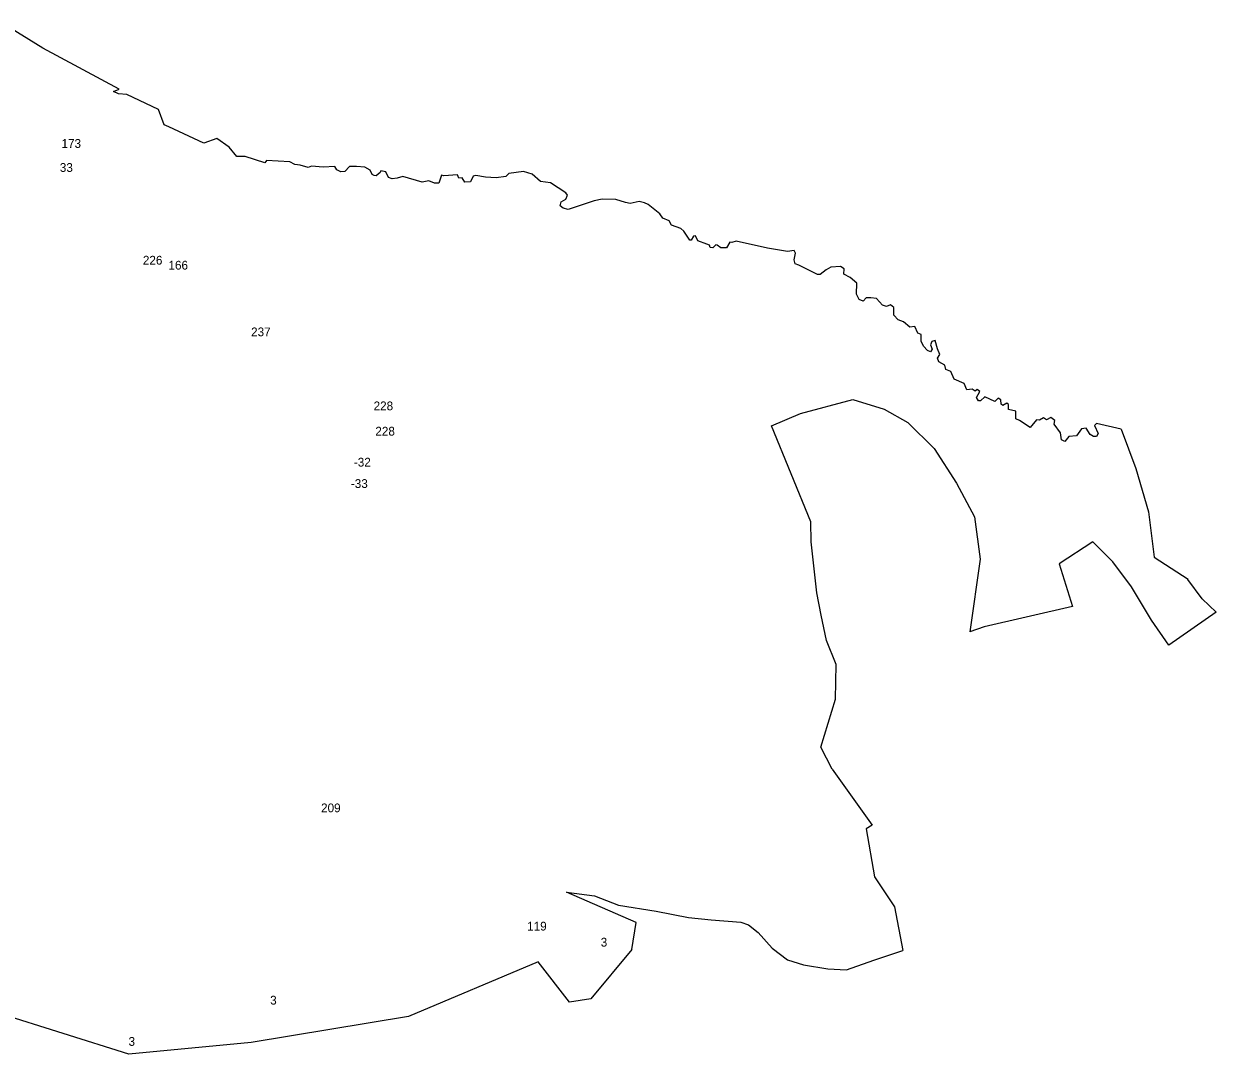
# Model space of a CAD drawing. Extents: x -788870 to -783053, y -967261 to -964403.
# Drawn here: x -784414 to -783053, y -967261 to -966085 of the extents above; entities that cross this region are included whole.
import ezdxf

# ---------------------------------------------------------------- set-up
doc = ezdxf.new("R2010")
doc.units = 0
doc.layers.add('Vrstva 13', color=7, linetype='Continuous')
doc.layers.add('Vrstva 15', color=7, linetype='Continuous')

msp = doc.modelspace()

# ---------------------------------------------------------------- linework, layer by layer
at = {"layer": 'Vrstva 13'}
for p, q in [((-784392.37, -966113.11), (-784437.41, -966085.29)), ((-784305.18, -966159.92), (-784392.37, -966113.11)), ((-784311.84, -966162.38), (-784305.18, -966159.92)), ((-784305.9, -966165.14), (-784311.84, -966162.38)), ((-784296.49, -966166.01), (-784305.9, -966165.14)), ((-784260.28, -966182.81), (-784296.49, -966166.01)), ((-784253.77, -966200.49), (-784260.28, -966182.81)), ((-784248.41, -966202.81), (-784253.77, -966200.49)), ((-784208.43, -966221.35), (-784248.41, -966202.81)), ((-784193.66, -966216.14), (-784208.43, -966221.35)), ((-784179.61, -966226.14), (-784193.66, -966216.14)), ((-784171.06, -966236.57), (-784179.61, -966226.14)), ((-784161.5, -966236.71), (-784171.06, -966236.57)), ((-784138.91, -966243.96), (-784161.5, -966236.71)), ((-784137.17, -966241.06), (-784138.91, -966243.96)), ((-784110.38, -966242.8), (-784137.17, -966241.06)), ((-784104.88, -966245.7), (-784110.38, -966242.8)), ((-784098.65, -966246.57), (-784104.88, -966245.7)), ((-784089.38, -966249.18), (-784098.65, -966246.57)), ((-784085.76, -966247.58), (-784089.38, -966249.18)), ((-784072.43, -966248.74), (-784085.76, -966247.58)), ((-784058.95, -966248.02), (-784072.43, -966248.74)), ((-784056.64, -966251.64), (-784058.95, -966248.02)), ((-784052.29, -966253.96), (-784056.64, -966251.64)), ((-784042.15, -966248.02), (-784047.51, -966253.53)), ((-784034.33, -966248.17), (-784042.15, -966248.02)), ((-784024.63, -966248.6), (-784034.33, -966248.17)), ((-784018.54, -966252.37), (-784024.63, -966248.6)), ((-784047.51, -966253.53), (-784052.29, -966253.96)), ((-784016.37, -966257), (-784018.54, -966252.37)), ((-784014.05, -966258.16), (-784016.37, -966257)), ((-784012.03, -966258.6), (-784014.05, -966258.16)), ((-784007.25, -966254.69), (-784012.03, -966258.6)), ((-784006.52, -966252.8), (-784007.25, -966254.69)), ((-784001.02, -966253.96), (-784006.52, -966252.8)), ((-783997.98, -966260.48), (-784001.02, -966253.96)), ((-783993.63, -966262.22), (-783997.98, -966260.48)), ((-783987.98, -966261.35), (-783993.63, -966262.22)), ((-783981.32, -966259.32), (-783987.98, -966261.35)), ((-783959.3, -966265.84), (-783981.32, -966259.32)), ((-783951.77, -966264.25), (-783959.3, -966265.84)), ((-783945.4, -966267.15), (-783951.77, -966264.25)), ((-783937.15, -966257.73), (-783940.48, -966266.86)), ((-783934.54, -966258.74), (-783937.15, -966257.73)), ((-783919.19, -966257.58), (-783934.54, -966258.74)), ((-783917.45, -966261.21), (-783919.19, -966257.58)), ((-783913.68, -966261.06), (-783917.45, -966261.21)), ((-783910.5, -966265.7), (-783913.68, -966261.06)), ((-783904.12, -966265.55), (-783910.5, -966265.7)), ((-783901.08, -966259.03), (-783904.12, -966265.55)), ((-783898.04, -966258.16), (-783901.08, -966259.03)), ((-783886.89, -966260.34), (-783898.04, -966258.16)), ((-783875.01, -966260.77), (-783886.89, -966260.34)), ((-783863.86, -966259.33), (-783875.01, -966260.77)), ((-783860.53, -966256.14), (-783863.86, -966259.33)), ((-783843.87, -966253.68), (-783860.53, -966256.14)), ((-783833.88, -966256.87), (-783843.87, -966253.68)), ((-783824.17, -966264.98), (-783833.88, -966256.87)), ((-783812.88, -966266.72), (-783824.17, -966264.98)), ((-783940.48, -966266.86), (-783945.4, -966267.15)), ((-783795.21, -966278.17), (-783812.88, -966266.72)), ((-783793.32, -966280.77), (-783795.21, -966278.17)), ((-783801.72, -966292.94), (-783800.56, -966288.16)), ((-783798.25, -966295.55), (-783801.72, -966292.94)), ((-783800.56, -966288.16), (-783795.35, -966285.12)), ((-783795.35, -966285.12), (-783793.32, -966280.77)), ((-783762.9, -966287), (-783792.89, -966297)), ((-783753.92, -966285.26), (-783762.9, -966287)), ((-783738.28, -966285.84), (-783753.92, -966285.26)), ((-783727.42, -966289.17), (-783738.28, -966285.84)), ((-783721.91, -966290.04), (-783727.42, -966289.17)), ((-783711.78, -966288.02), (-783721.91, -966290.04)), ((-783705.69, -966289.46), (-783711.78, -966288.02)), ((-783701.49, -966291.35), (-783705.69, -966289.46)), ((-783687.88, -966301.93), (-783701.49, -966291.35)), ((-783792.89, -966297), (-783798.25, -966295.55)), ((-783684.55, -966307.14), (-783687.88, -966301.93)), ((-783677.3, -966309.89), (-783684.55, -966307.14)), ((-783674.69, -966315.12), (-783677.3, -966309.89)), ((-783664.12, -966318.74), (-783674.69, -966315.12)), ((-783660.64, -966321.64), (-783664.12, -966318.74)), ((-783653.83, -966332.21), (-783660.64, -966321.64)), ((-783652.38, -966332.21), (-783653.83, -966332.21)), ((-783649.49, -966327.58), (-783652.38, -966332.21)), ((-783647.32, -966327.29), (-783649.49, -966327.58)), ((-783644.56, -966332.65), (-783647.32, -966327.29)), ((-783634.28, -966336.56), (-783644.56, -966332.65)), ((-783600.97, -966333.23), (-783605.75, -966334.68)), ((-783565.19, -966341.34), (-783600.97, -966333.23)), ((-783631.24, -966337.86), (-783634.28, -966336.56)), ((-783630.8, -966340.47), (-783631.24, -966337.86)), ((-783627.62, -966340.91), (-783630.8, -966340.47)), ((-783624.29, -966337.28), (-783627.62, -966340.91)), ((-783622.55, -966337.72), (-783624.29, -966337.28)), ((-783618.49, -966340.91), (-783622.55, -966337.72)), ((-783611.97, -966340.76), (-783618.49, -966340.91)), ((-783608.21, -966334.24), (-783611.97, -966340.76)), ((-783605.75, -966334.68), (-783608.21, -966334.24)), ((-783542.31, -966345.11), (-783565.19, -966341.34)), ((-783534.63, -966343.66), (-783542.31, -966345.11)), ((-783533.03, -966346.85), (-783534.63, -966343.66)), ((-783534.63, -966354.67), (-783533.03, -966346.85)), ((-783533.61, -966359.16), (-783534.63, -966354.67)), ((-783529.41, -966360.47), (-783533.61, -966359.16)), ((-783507.98, -966371.19), (-783529.41, -966360.47)), ((-783504.94, -966371.33), (-783507.98, -966371.19)), ((-783498.27, -966365.83), (-783504.94, -966371.33)), ((-783493.06, -966362.79), (-783498.27, -966365.83)), ((-783481.76, -966361.92), (-783493.06, -966362.79)), ((-783477.56, -966364.67), (-783481.76, -966361.92)), ((-783477.85, -966370.76), (-783477.56, -966364.67)), ((-783470.75, -966374.67), (-783477.85, -966370.76)), ((-783463.22, -966381.19), (-783470.75, -966374.67)), ((-783463.51, -966393.79), (-783463.22, -966381.19)), ((-783460.47, -966399.59), (-783463.51, -966393.79)), ((-783455.98, -966401.47), (-783460.47, -966399.59)), ((-783452.5, -966398), (-783455.98, -966401.47)), ((-783447.29, -966398), (-783452.5, -966398)), ((-783440.62, -966398.57), (-783447.29, -966398)), ((-783433.81, -966406.1), (-783440.62, -966398.57)), ((-783429.46, -966407.55), (-783433.81, -966406.1)), ((-783424.83, -966405.96), (-783429.46, -966407.55)), ((-783420.92, -966409), (-783424.83, -966405.96)), ((-783421.06, -966417.55), (-783420.92, -966409)), ((-783416.14, -966422.91), (-783421.06, -966417.55)), ((-783409.91, -966425.08), (-783416.14, -966422.91)), ((-783402.52, -966431.46), (-783409.91, -966425.08)), ((-783396.88, -966430.59), (-783402.52, -966431.46)), ((-783393.69, -966438.27), (-783396.88, -966430.59)), ((-783389.92, -966439.71), (-783393.69, -966438.27)), ((-783389.63, -966447.25), (-783389.92, -966439.71)), ((-783387.03, -966453.04), (-783389.63, -966447.25)), ((-783382.54, -966458.11), (-783387.03, -966453.04)), ((-783377.32, -966456.23), (-783379.21, -966459.42)), ((-783377.47, -966447.54), (-783379.06, -966451.3)), ((-783379.06, -966451.3), (-783377.32, -966456.23)), ((-783373.85, -966446.67), (-783377.47, -966447.54)), ((-783371.24, -966456.08), (-783373.85, -966446.67)), ((-783368.34, -966462.31), (-783371.24, -966456.08)), ((-783379.21, -966459.42), (-783382.54, -966458.11)), ((-783371.24, -966466.66), (-783368.34, -966462.31)), ((-783369.65, -966470.86), (-783371.24, -966466.66)), ((-783362.69, -966474.49), (-783369.65, -966470.86)), ((-783361.68, -966479.7), (-783362.69, -966474.49)), ((-783356.03, -966482.02), (-783361.68, -966479.7)), ((-783352.12, -966490.57), (-783356.03, -966482.02)), ((-783340.83, -966495.64), (-783352.12, -966490.57)), ((-783337.78, -966502.74), (-783340.83, -966495.64)), ((-783331.7, -966502.16), (-783337.78, -966502.74)), ((-783327.94, -966504.33), (-783331.7, -966502.16)), ((-783325.76, -966502.3), (-783327.94, -966504.33)), ((-783326.63, -966511.43), (-783322.72, -966504.77)), ((-783322.72, -966504.77), (-783325.76, -966502.3)), ((-783316.93, -966510.71), (-783321.85, -966515.49)), ((-783305.63, -966516.21), (-783316.93, -966510.71)), ((-783527.66, -966529.62), (-783467.62, -966513.72)), ((-783467.62, -966513.72), (-783431.85, -966524.77)), ((-783324.46, -966515.34), (-783326.63, -966511.43)), ((-783321.85, -966515.49), (-783324.46, -966515.34)), ((-783301.72, -966512.45), (-783305.63, -966516.21)), ((-783298.68, -966514.04), (-783301.72, -966512.45)), ((-783298.53, -966519.26), (-783298.68, -966514.04)), ((-783296.65, -966520.7), (-783298.53, -966519.26)), ((-783292.01, -966518.1), (-783296.65, -966520.7)), ((-783289.99, -966519.4), (-783292.01, -966518.1)), ((-783290.13, -966525.05), (-783289.99, -966519.4)), ((-783560.78, -966543.76), (-783527.66, -966529.62)), ((-783431.85, -966524.77), (-783404.92, -966540.22)), ((-783281.88, -966527.22), (-783290.13, -966525.05)), ((-783281.73, -966535.77), (-783281.88, -966527.22)), ((-783277.53, -966537.95), (-783281.73, -966535.77)), ((-783265.36, -966545.77), (-783277.53, -966537.95)), ((-783257.98, -966537.08), (-783265.36, -966545.77)), ((-783254.5, -966537.51), (-783257.98, -966537.08)), ((-783250.3, -966534.76), (-783254.5, -966537.51)), ((-783246.53, -966537.08), (-783250.3, -966534.76)), ((-783241.9, -966534.47), (-783246.53, -966537.08)), ((-783237.27, -966537.8), (-783241.9, -966534.47)), ((-783238.13, -966542.15), (-783237.27, -966537.8)), ((-783515.74, -966653.29), (-783560.78, -966543.76)), ((-783404.92, -966540.22), (-783374.9, -966569.82)), ((-783230.75, -966551.71), (-783238.13, -966542.15)), ((-783206.56, -966547.22), (-783212.35, -966555.19)), ((-783201.49, -966546.49), (-783206.56, -966547.22)), ((-783196.86, -966553.74), (-783201.49, -966546.49)), ((-783189.61, -966541.28), (-783191.79, -966543.45)), ((-783191.79, -966543.45), (-783187.73, -966552.58)), ((-783161.37, -966547.51), (-783189.61, -966541.28)), ((-783161.37, -966547.51), (-783144.87, -966592.57)), ((-783229.59, -966559.83), (-783230.75, -966551.71)), ((-783225.68, -966561.71), (-783229.59, -966559.83)), ((-783221.33, -966555.91), (-783225.68, -966561.71)), ((-783212.35, -966555.19), (-783221.33, -966555.91)), ((-783193.23, -966555.91), (-783196.86, -966553.74)), ((-783189.47, -966555.91), (-783193.23, -966555.91)), ((-783187.73, -966552.58), (-783189.47, -966555.91)), ((-783374.9, -966569.82), (-783349.29, -966609.13)), ((-783144.87, -966592.57), (-783130.3, -966642.04)), ((-783349.29, -966609.13), (-783328.98, -966647.55)), ((-783130.3, -966642.04), (-783123.67, -966693.72)), ((-783515.3, -966676.26), (-783515.74, -966653.29)), ((-783328.98, -966647.55), (-783322.36, -966696.14)), ((-783508.68, -966734.56), (-783515.3, -966676.26)), ((-783193.77, -966676.16), (-783232.4, -966701.12)), ((-783171.03, -966699.13), (-783193.77, -966676.16)), ((-783322.36, -966696.14), (-783334.28, -966778.73)), ((-783232.4, -966701.12), (-783217.17, -966749.92)), ((-783149.62, -966727.4), (-783171.03, -966699.13)), ((-783123.67, -966693.72), (-783084.81, -966718.67)), ((-783126.93, -966765.55), (-783149.62, -966727.4)), ((-783084.81, -966718.67), (-783085.2, -966719.35)), ((-783068.97, -966741.38), (-783085.2, -966719.35)), ((-783503.82, -966759.74), (-783508.68, -966734.56)), ((-783053.04, -966756.45), (-783068.97, -966741.38)), ((-783217.17, -966749.92), (-783317.94, -966772.99)), ((-783497.64, -966788.89), (-783503.82, -966759.74)), ((-783106.92, -966794.12), (-783126.93, -966765.55)), ((-783053.04, -966756.45), (-783106.92, -966794.12)), ((-783317.94, -966772.99), (-783334.28, -966778.73)), ((-783486.82, -966816.06), (-783497.64, -966788.89)), ((-783487.71, -966855.81), (-783486.82, -966816.06)), ((-783504.48, -966910.58), (-783487.71, -966855.81)), ((-783491.34, -966935.65), (-783504.48, -966910.58)), ((-783491.34, -966935.65), (-783445.57, -966999.4)), ((-783445.57, -966999.4), (-783452.52, -967003.75)), ((-783452.52, -967003.75), (-783442.96, -967058.23)), ((-783442.96, -967058.23), (-783420.36, -967092.74)), ((-783714.97, -967110.41), (-783794.64, -967075.92)), ((-783794.64, -967075.92), (-783762.77, -967079.98)), ((-783762.77, -967079.98), (-783735.25, -967090.7)), ((-783735.25, -967090.7), (-783692.09, -967097.37)), ((-783420.36, -967092.74), (-783410.81, -967142.57)), ((-783692.09, -967097.37), (-783655.3, -967104.61)), ((-783655.3, -967104.61), (-783629.52, -967107.51)), ((-783629.52, -967107.51), (-783595.63, -967110.12)), ((-783719.9, -967141.42), (-783714.97, -967110.41)), ((-783595.63, -967110.12), (-783586.94, -967113.02)), ((-783586.94, -967113.02), (-783575.64, -967122)), ((-783575.64, -967122), (-783559.99, -967139.67)), ((-783719.9, -967141.42), (-783766.83, -967197.48)), ((-783559.99, -967139.67), (-783542.32, -967153.15)), ((-783443.69, -967153.29), (-783410.81, -967142.57)), ((-783826.8, -967155.17), (-783974.82, -967217.76)), ((-783791.16, -967201.24), (-783826.8, -967155.17)), ((-783542.32, -967153.15), (-783523.93, -967158.8)), ((-783523.93, -967158.8), (-783496.26, -967163.44)), ((-783496.26, -967163.44), (-783474.97, -967164.45)), ((-783474.97, -967164.45), (-783443.69, -967153.29)), ((-784294.33, -967260.65), (-784481.47, -967201.83)), ((-783766.83, -967197.48), (-783791.16, -967201.24)), ((-783974.82, -967217.76), (-784154.42, -967247.32)), ((-784154.42, -967247.32), (-784294.33, -967260.65))]:
    msp.add_line(p, q, dxfattribs=at)

# ---------------------------------------------------------------- texts
at = {"layer": 'Vrstva 15'}
for s, p in [('173', (-784371.03, -966226.74)), ('33', (-784372.966, -966254.14)), ('226', (-784278.18, -966359.94)), ('166', (-784248.958, -966365.62)), ('237', (-784154.656, -966441.71)), ('228', (-784014.806, -966526.1)), ('228', (-784012.826, -966555)), ('-32', (-784037.35, -966590.35)), ('-33', (-784040.76, -966614.74)), ('209', (-784074.76, -966984.73)), ('119', (-783839.529, -967119.66)), ('3', (-783755.566, -967137.93)), ('3', (-784132.846, -967204.1)), ('3', (-784294.536, -967251.16))]:
    msp.add_text(s, height=10, dxfattribs=at).set_placement(p)

doc.saveas('drawing.dxf')
